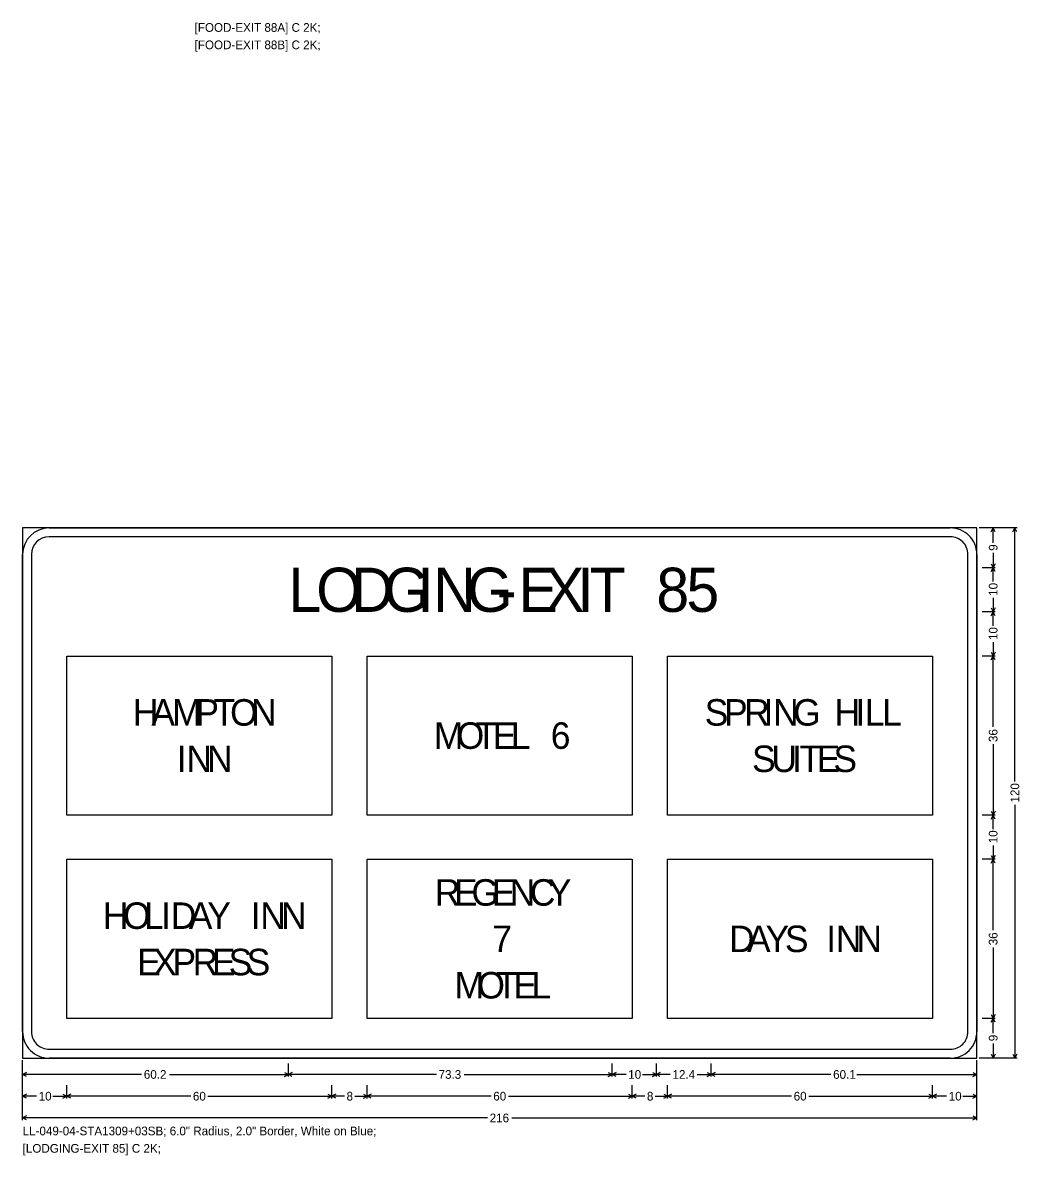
# Model space of a CAD drawing. Extents: x 667331 to 731245, y 738830 to 753817.
# Drawn here: x 729601.2 to 730007.3, y 746317.4 to 746778.9 of the extents above; entities that cross this region are included whole.
import ezdxf

# ---------------------------------------------------------------- set-up
doc = ezdxf.new("R2010")
doc.units = 0
doc.layers.add('R_SIGN', color=7, linetype='Continuous')

msp = doc.modelspace()

# ---------------------------------------------------------------- linework, layer by layer
at = {"layer": 'R_SIGN'}
for p, q in [((730006.41, 746573.02), (729990.91, 746573.02)), ((729997.55, 746573.02), (729992.24, 746573.02)), ((729995.87, 746571.44), (729996.67, 746573.02)), ((729996.67, 746567.02), (729996.67, 746573.02)), ((729997.46, 746571.44), (729996.67, 746573.02)), ((730004.73, 746571.44), (730005.52, 746573.02)), ((730005.52, 746469.79), (730005.52, 746573.02)), ((730006.32, 746571.44), (730005.52, 746573.02)), ((729996.67, 746562.82), (729996.67, 746556.82)), ((729995.87, 746558.41), (729996.67, 746556.82)), ((729997.46, 746558.41), (729996.67, 746556.82)), ((729997.55, 746556.82), (729992.24, 746556.82)), ((729995.87, 746555.24), (729996.67, 746556.82)), ((729996.67, 746551.17), (729996.67, 746556.82)), ((729997.46, 746555.24), (729996.67, 746556.82)), ((729996.67, 746544.48), (729996.67, 746538.82)), ((729995.87, 746540.41), (729996.67, 746538.82)), ((729997.46, 746540.41), (729996.67, 746538.82)), ((729997.55, 746538.82), (729992.24, 746538.82)), ((729995.87, 746537.24), (729996.67, 746538.82)), ((729996.67, 746533.17), (729996.67, 746538.82)), ((729997.46, 746537.24), (729996.67, 746538.82)), ((729996.67, 746526.48), (729996.67, 746520.82)), ((729619.22, 746456.02), (729619.22, 746520.82)), ((729619.22, 746520.82), (729727.22, 746520.82)), ((729727.22, 746520.82), (729727.22, 746456.02)), ((729741.62, 746456.02), (729741.62, 746520.82)), ((729741.62, 746520.82), (729849.62, 746520.82)), ((729849.62, 746520.82), (729849.62, 746456.02)), ((729864.02, 746456.02), (729864.02, 746520.82)), ((729864.02, 746520.82), (729972.02, 746520.82)), ((729972.02, 746520.82), (729972.02, 746456.02)), ((729997.55, 746520.82), (729992.24, 746520.82)), ((729995.87, 746522.41), (729996.67, 746520.82)), ((729995.87, 746519.24), (729996.67, 746520.82)), ((729997.46, 746522.41), (729996.67, 746520.82)), ((729996.67, 746491.95), (729996.67, 746520.82)), ((729997.46, 746519.24), (729996.67, 746520.82)), ((729996.67, 746484.89), (729996.67, 746456.02)), ((729727.22, 746456.02), (729619.22, 746456.02)), ((729849.62, 746456.02), (729741.62, 746456.02)), ((729972.02, 746456.02), (729864.02, 746456.02)), ((729997.55, 746456.02), (729992.24, 746456.02)), ((729995.87, 746457.61), (729996.67, 746456.02)), ((729995.87, 746454.44), (729996.67, 746456.02)), ((729997.46, 746457.61), (729996.67, 746456.02)), ((729996.67, 746450.37), (729996.67, 746456.02)), ((729997.46, 746454.44), (729996.67, 746456.02)), ((730005.52, 746460.26), (730005.52, 746357.02)), ((729996.67, 746443.68), (729996.67, 746438.02)), ((729619.22, 746373.22), (729619.22, 746438.02)), ((729619.22, 746438.02), (729727.22, 746438.02)), ((729727.22, 746438.02), (729727.22, 746373.22)), ((729741.62, 746373.22), (729741.62, 746438.02)), ((729741.62, 746438.02), (729849.62, 746438.02)), ((729849.62, 746438.02), (729849.62, 746373.22)), ((729864.02, 746373.22), (729864.02, 746438.02)), ((729864.02, 746438.02), (729972.02, 746438.02)), ((729972.02, 746438.02), (729972.02, 746373.22)), ((729997.55, 746438.02), (729992.24, 746438.02)), ((729995.87, 746439.61), (729996.67, 746438.02)), ((729995.87, 746436.44), (729996.67, 746438.02)), ((729997.46, 746439.61), (729996.67, 746438.02)), ((729996.67, 746409.15), (729996.67, 746438.02)), ((729997.46, 746436.44), (729996.67, 746438.02)), ((729996.67, 746402.09), (729996.67, 746373.22)), ((729727.22, 746373.22), (729619.22, 746373.22)), ((729849.62, 746373.22), (729741.62, 746373.22)), ((729972.02, 746373.22), (729864.02, 746373.22)), ((729997.55, 746373.22), (729992.24, 746373.22)), ((729997.55, 746373.22), (729992.24, 746373.22)), ((729995.87, 746374.81), (729996.67, 746373.22)), ((729995.87, 746371.64), (729996.67, 746373.22)), ((729997.46, 746374.81), (729996.67, 746373.22)), ((729996.67, 746367.22), (729996.67, 746373.22)), ((729997.46, 746371.64), (729996.67, 746373.22)), ((729996.67, 746363.02), (729996.67, 746357.02)), ((729601.22, 746331.78), (729601.22, 746356.14)), ((729601.22, 746349.49), (729601.22, 746354.81)), ((729709.49, 746349.49), (729709.49, 746354.81)), ((729841.43, 746349.49), (729841.43, 746354.81)), ((729859.43, 746349.49), (729859.43, 746354.81)), ((729881.75, 746349.49), (729881.75, 746354.81)), ((729881.75, 746349.49), (729881.75, 746354.81)), ((729990.02, 746331.78), (729990.02, 746356.14)), ((729990.02, 746349.49), (729990.02, 746354.81)), ((730006.41, 746357.02), (729990.91, 746357.02)), ((729997.55, 746357.02), (729992.24, 746357.02)), ((729995.87, 746358.61), (729996.67, 746357.02)), ((729997.46, 746358.61), (729996.67, 746357.02)), ((730004.73, 746358.61), (730005.52, 746357.02)), ((730006.32, 746358.61), (730005.52, 746357.02)), ((729602.81, 746351.17), (729601.22, 746350.38)), ((729649.71, 746350.38), (729601.22, 746350.38)), ((729602.81, 746349.59), (729601.22, 746350.38)), ((729661, 746350.38), (729709.49, 746350.38)), ((729707.91, 746351.17), (729709.49, 746350.38)), ((729707.91, 746349.59), (729709.49, 746350.38)), ((729711.08, 746351.17), (729709.49, 746350.38)), ((729769.82, 746350.38), (729709.49, 746350.38)), ((729711.08, 746349.59), (729709.49, 746350.38)), ((729781.11, 746350.38), (729841.43, 746350.38)), ((729839.85, 746351.17), (729841.43, 746350.38)), ((729839.85, 746349.59), (729841.43, 746350.38)), ((729843.02, 746351.17), (729841.43, 746350.38)), ((729847.09, 746350.38), (729841.43, 746350.38)), ((729843.02, 746349.59), (729841.43, 746350.38)), ((729853.78, 746350.38), (729859.43, 746350.38)), ((729857.85, 746351.17), (729859.43, 746350.38)), ((729857.85, 746349.59), (729859.43, 746350.38)), ((729861.02, 746351.17), (729859.43, 746350.38)), ((729865.12, 746350.38), (729859.43, 746350.38)), ((729861.02, 746349.59), (729859.43, 746350.38)), ((729876.06, 746350.38), (729881.75, 746350.38)), ((729880.17, 746351.17), (729881.75, 746350.38)), ((729880.17, 746349.59), (729881.75, 746350.38)), ((729883.34, 746351.17), (729881.75, 746350.38)), ((729930.59, 746350.38), (729881.75, 746350.38)), ((729883.34, 746349.59), (729881.75, 746350.38)), ((729941.19, 746350.38), (729990.02, 746350.38)), ((729988.44, 746351.17), (729990.02, 746350.38)), ((729988.44, 746349.59), (729990.02, 746350.38)), ((729601.22, 746340.64), (729601.22, 746345.95)), ((729619.22, 746340.64), (729619.22, 746345.95)), ((729727.22, 746340.64), (729727.22, 746345.95)), ((729741.62, 746340.64), (729741.62, 746345.95)), ((729849.62, 746340.64), (729849.62, 746345.95)), ((729864.02, 746340.64), (729864.02, 746345.95)), ((729972.02, 746340.64), (729972.02, 746345.95)), ((729972.02, 746340.64), (729972.02, 746345.95)), ((729990.02, 746340.64), (729990.02, 746345.95)), ((729602.81, 746342.31), (729601.22, 746341.52)), ((729606.88, 746341.52), (729601.22, 746341.52)), ((729602.81, 746340.73), (729601.22, 746341.52)), ((729613.57, 746341.52), (729619.22, 746341.52)), ((729617.64, 746342.31), (729619.22, 746341.52)), ((729617.64, 746340.73), (729619.22, 746341.52)), ((729620.81, 746342.31), (729619.22, 746341.52)), ((729669.7, 746341.52), (729619.22, 746341.52)), ((729620.81, 746340.73), (729619.22, 746341.52)), ((729676.74, 746341.52), (729727.22, 746341.52)), ((729725.64, 746342.31), (729727.22, 746341.52)), ((729725.64, 746340.73), (729727.22, 746341.52)), ((729728.81, 746342.31), (729727.22, 746341.52)), ((729732.31, 746341.52), (729727.22, 746341.52)), ((729728.81, 746340.73), (729727.22, 746341.52)), ((729736.53, 746341.52), (729741.62, 746341.52)), ((729740.04, 746342.31), (729741.62, 746341.52)), ((729740.04, 746340.73), (729741.62, 746341.52)), ((729743.21, 746342.31), (729741.62, 746341.52)), ((729792.1, 746341.52), (729741.62, 746341.52)), ((729743.21, 746340.73), (729741.62, 746341.52)), ((729799.14, 746341.52), (729849.62, 746341.52)), ((729848.04, 746342.31), (729849.62, 746341.52)), ((729848.04, 746340.73), (729849.62, 746341.52)), ((729851.21, 746342.31), (729849.62, 746341.52)), ((729854.71, 746341.52), (729849.62, 746341.52)), ((729851.21, 746340.73), (729849.62, 746341.52)), ((729858.93, 746341.52), (729864.02, 746341.52)), ((729862.44, 746342.31), (729864.02, 746341.52)), ((729862.44, 746340.73), (729864.02, 746341.52)), ((729865.61, 746342.31), (729864.02, 746341.52)), ((729914.5, 746341.52), (729864.02, 746341.52)), ((729865.61, 746340.73), (729864.02, 746341.52)), ((729921.54, 746341.52), (729972.02, 746341.52)), ((729970.44, 746342.31), (729972.02, 746341.52)), ((729970.44, 746340.73), (729972.02, 746341.52)), ((729973.61, 746342.31), (729972.02, 746341.52)), ((729977.68, 746341.52), (729972.02, 746341.52)), ((729973.61, 746340.73), (729972.02, 746341.52)), ((729984.37, 746341.52), (729990.02, 746341.52)), ((729988.44, 746342.31), (729990.02, 746341.52)), ((729988.44, 746340.73), (729990.02, 746341.52)), ((729602.81, 746333.46), (729601.22, 746332.66)), ((729790.64, 746332.66), (729601.22, 746332.66)), ((729602.81, 746331.87), (729601.22, 746332.66)), ((729800.61, 746332.66), (729990.02, 746332.66)), ((729988.44, 746333.46), (729990.02, 746332.66)), ((729988.44, 746331.87), (729990.02, 746332.66))]:
    msp.add_line(p, q, dxfattribs=at)
for points in [[(729601.22, 746357.02), (729990.02, 746357.02), (729990.02, 746573.02), (729601.22, 746573.02), (729601.22, 746357.02), (729601.22, 746357.02)], [(729612.02, 746573.02), (729979.22, 746573.02)], [(729979.22, 746569.42), (729612.02, 746569.42)], [(729601.22, 746367.82), (729601.22, 746562.22)], [(729604.82, 746562.22), (729604.82, 746367.82)], [(729986.42, 746367.82), (729986.42, 746562.22)], [(729990.02, 746562.22), (729990.02, 746367.82)], [(729612.02, 746360.62), (729979.22, 746360.62)], [(729979.22, 746357.02), (729612.02, 746357.02)]]:
    msp.add_lwpolyline(points, dxfattribs=at)
for centre, radius, start, end in [((729612.02, 746562.22), 10.8, 90.0002, 179.9998), ((729979.22, 746562.22), 10.8, 0, 90.0002), ((729612.02, 746562.22), 7.2, 90.0002, 179.9998), ((729979.22, 746562.22), 7.2, 0, 90.0002), ((729612.02, 746367.82), 10.8, 179.9998, 270.0001), ((729612.02, 746367.82), 7.2, 179.9998, 270.0001), ((729979.22, 746367.82), 10.8, 270.0001, 0.0003), ((729979.22, 746367.82), 7.2, 270.0001, 0.0003)]:
    msp.add_arc(centre, radius, start, end, dxfattribs=at)

# ---------------------------------------------------------------- texts
for s, height, p in [('[FOOD-EXIT 88A] C 2K; ', 3.5433, (729671.3, 746775.13)), ('[FOOD-EXIT 88B] C 2K; ', 3.5433, (729671.3, 746768.05)), ('L', 18, (729709.49, 746538.82)), ('O', 18, (729720.83, 746538.82)), ('D', 18, (729735.05, 746538.82)), ('G', 18, (729748.37, 746538.82)), ('I', 18, (729762.05, 746538.82)), ('N', 18, (729768.53, 746538.82)), ('G', 18, (729782.21, 746538.82)), ('E', 18, (729803.27, 746538.82)), ('X', 18, (729814.07, 746538.82)), ('I', 18, (729827.21, 746538.82)), ('T', 18, (729832.25, 746538.82)), ('8', 18, (729859.43, 746538.82)), ('5', 18, (729871.67, 746538.82)), ('-', 18, (729794.45, 746538.82)), ('H', 10.8, (729646.11, 746492.47)), ('A', 10.8, (729653.67, 746492.47)), ('M', 10.8, (729662.1, 746492.47)), ('P', 10.8, (729671.6, 746492.47)), ('T', 10.8, (729678.95, 746492.47)), ('O', 10.8, (729685.75, 746492.47)), ('N', 10.8, (729694.28, 746492.47)), ('S', 10.8, (729879.14, 746492.47)), ('P', 10.8, (729887.03, 746492.47)), ('R', 10.8, (729895.23, 746492.47)), ('I', 10.8, (729903.12, 746492.47)), ('N', 10.8, (729907.01, 746492.47)), ('G', 10.8, (729915.21, 746492.47)), ('H', 10.8, (729932.06, 746492.47)), ('I', 10.8, (729940.49, 746492.47)), ('L', 10.8, (729944.37, 746492.47)), ('L', 10.8, (729951.39, 746492.47)), ('M', 10.8, (729768.78, 746483.02)), ('O', 10.8, (729778.07, 746483.02)), ('T', 10.8, (729785.74, 746483.02)), ('E', 10.8, (729792.76, 746483.02)), ('L', 10.8, (729800.1, 746483.02)), ('6', 10.8, (729816.41, 746483.02)), ('I', 10.8, (729664.04, 746473.57)), ('N', 10.8, (729667.93, 746473.57)), ('N', 10.8, (729676.35, 746473.57)), ('S', 10.8, (729898.42, 746473.57)), ('U', 10.8, (729906.3, 746473.57)), ('I', 10.8, (729914.73, 746473.57)), ('T', 10.8, (729917.75, 746473.57)), ('E', 10.8, (729924.77, 746473.57)), ('S', 10.8, (729931.58, 746473.57)), ('R', 10.8, (729769.11, 746419.12)), ('E', 10.8, (729776.99, 746419.12)), ('G', 10.8, (729784.12, 746419.12)), ('E', 10.8, (729792.33, 746419.12)), ('N', 10.8, (729799.67, 746419.12)), ('C', 10.8, (729807.88, 746419.12)), ('Y', 10.8, (729815.22, 746419.12)), ('H', 10.8, (729633.91, 746409.67)), ('O', 10.8, (729642.12, 746409.67)), ('L', 10.8, (729650.65, 746409.67)), ('I', 10.8, (729657.67, 746409.67)), ('D', 10.8, (729661.56, 746409.67)), ('A', 10.8, (729668.9, 746409.67)), ('Y', 10.8, (729676.46, 746409.67)), ('I', 10.8, (729694.17, 746409.67)), ('N', 10.8, (729698.06, 746409.67)), ('N', 10.8, (729706.49, 746409.67)), ('7', 10.8, (729792.6, 746400.22)), ('D', 10.8, (729889.02, 746400.22)), ('A', 10.8, (729896.37, 746400.22)), ('Y', 10.8, (729903.93, 746400.22)), ('S', 10.8, (729911.81, 746400.22)), ('I', 10.8, (729928.66, 746400.22)), ('N', 10.8, (729932.55, 746400.22)), ('N', 10.8, (729940.97, 746400.22)), ('E', 10.8, (729647.9, 746390.77)), ('X', 10.8, (729654.38, 746390.77)), ('P', 10.8, (729662.26, 746390.77)), ('R', 10.8, (729670.47, 746390.77)), ('E', 10.8, (729678.35, 746390.77)), ('S', 10.8, (729685.16, 746390.77)), ('S', 10.8, (729692.5, 746390.77)), ('M', 10.8, (729777.21, 746381.32)), ('O', 10.8, (729786.5, 746381.32)), ('T', 10.8, (729794.16, 746381.32)), ('E', 10.8, (729801.18, 746381.32)), ('L', 10.8, (729808.53, 746381.32)), ('60.2', 3.543, (729650.6, 746348.61)), ('73.3', 3.543, (729770.7, 746348.61)), ('10', 3.543, (729847.97, 746348.61)), ('12.4', 3.543, (729866.01, 746348.61)), ('60.1', 3.543, (729931.47, 746348.61)), ('10', 3.543, (729607.76, 746339.75)), ('60', 3.543, (729670.59, 746339.75)), ('8', 3.54, (729733.2, 746339.75)), ('60', 3.543, (729792.99, 746339.75)), ('8', 3.54, (729855.6, 746339.75)), ('60', 3.543, (729915.39, 746339.75)), ('10', 3.543, (729978.56, 746339.75)), ('216', 3.543, (729791.52, 746330.89)), ('LL-049-04-STA1309+03SB; 6.0" Radius, 2.0" Border, White on Blue; ', 3.5433, (729601.22, 746325.58)), ('[LODGING-EXIT 85] C 2K; ', 3.5433, (729601.22, 746318.49))]:
    msp.add_text(s, height=height, dxfattribs=at).set_placement(p)
for s, height, p in [('9', 3.54, (729998.44, 746563.71)), ('10', 3.543, (729998.44, 746545.36)), ('10', 3.543, (729998.44, 746527.36)), ('36', 3.543, (729998.44, 746485.78)), ('120', 3.543, (730007.29, 746461.15)), ('10', 3.543, (729998.44, 746444.56)), ('36', 3.543, (729998.44, 746402.98)), ('9', 3.54, (729998.44, 746363.91))]:
    msp.add_text(s, height=height, rotation=90.0002, dxfattribs=at).set_placement(p)

doc.saveas('drawing.dxf')
